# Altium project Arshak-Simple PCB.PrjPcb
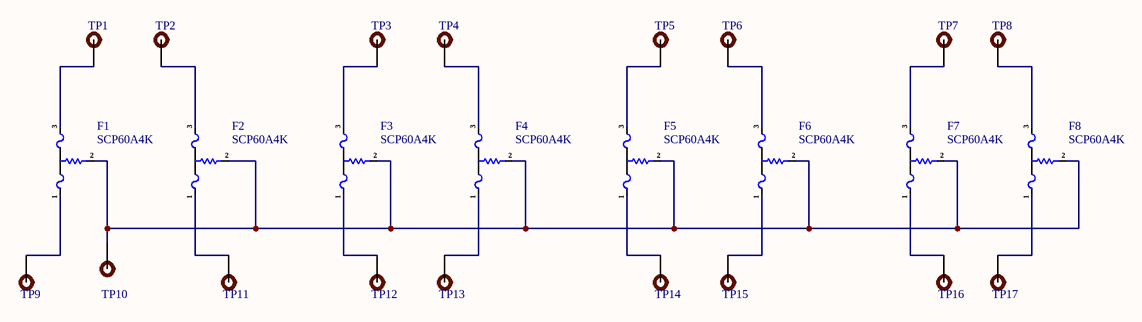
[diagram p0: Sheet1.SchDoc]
1 sheet, 25 parts. Net scope: global (net labels, ports and power ports of the same name join across sheets).
Board file: PCB1.PcbDoc

## Sheet Sheet1.SchDoc
size A4; SheetNumber: 1; SheetTotal: 1

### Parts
F1  SCP60A4K  [SCP60a4k]
F2  SCP60A4K  [SCP60a4k]
F3  SCP60A4K  [SCP60a4k]
F4  SCP60A4K  [SCP60a4k]
F5  SCP60A4K  [SCP60a4k]
F6  SCP60A4K  [SCP60a4k]
F7  SCP60A4K  [SCP60a4k]
F8  SCP60A4K  [SCP60a4k]
TP1  3x4mm Test Pad SMD  [3x4mm Test Pad SMD]  (value not drawn)
TP2  3x4mm Test Pad SMD  [3x4mm Test Pad SMD]  (value not drawn)
TP3  3x4mm Test Pad SMD  [3x4mm Test Pad SMD]  (value not drawn)
TP4  3x4mm Test Pad SMD  [3x4mm Test Pad SMD]  (value not drawn)
TP5  3x4mm Test Pad SMD  [3x4mm Test Pad SMD]  (value not drawn)
TP6  3x4mm Test Pad SMD  [3x4mm Test Pad SMD]  (value not drawn)
TP7  3x4mm Test Pad SMD  [3x4mm Test Pad SMD]  (value not drawn)
TP8  3x4mm Test Pad SMD  [3x4mm Test Pad SMD]  (value not drawn)
TP9  3x4mm Test Pad SMD  [3x4mm Test Pad SMD]  (value not drawn)
TP10  10X10MM TEST PAD SMD  [10X10MM TEST PAD SMD]  (value not drawn)
TP11  3x4mm Test Pad SMD  [3x4mm Test Pad SMD]  (value not drawn)
TP12  3x4mm Test Pad SMD  [3x4mm Test Pad SMD]  (value not drawn)
TP13  3x4mm Test Pad SMD  [3x4mm Test Pad SMD]  (value not drawn)
TP14  3x4mm Test Pad SMD  [3x4mm Test Pad SMD]  (value not drawn)
TP15  3x4mm Test Pad SMD  [3x4mm Test Pad SMD]  (value not drawn)
TP16  3x4mm Test Pad SMD  [3x4mm Test Pad SMD]  (value not drawn)
TP17  3x4mm Test Pad SMD  [3x4mm Test Pad SMD]  (value not drawn)

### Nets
NetF1_1: F1.1 TP9.1
NetF1_2: F1.2 F2.2 F3.2 F4.2 F5.2 F6.2 F7.2 F8.2 TP10.1
NetF1_3: F1.3 TP1.1
NetF2_1: F2.1 TP11.1
NetF2_3: F2.3 TP2.1
NetF3_1: F3.1 TP12.1
NetF3_3: F3.3 TP3.1
NetF4_1: F4.1 TP13.1
NetF4_3: F4.3 TP4.1
NetF5_1: F5.1 TP14.1
NetF5_3: F5.3 TP5.1
NetF6_1: F6.1 TP15.1
NetF6_3: F6.3 TP6.1
NetF7_1: F7.1 TP16.1
NetF7_3: F7.3 TP7.1
NetF8_1: F8.1 TP17.1
NetF8_3: F8.3 TP8.1

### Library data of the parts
F1-F8 = SCP60A4K: Self Control Protector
